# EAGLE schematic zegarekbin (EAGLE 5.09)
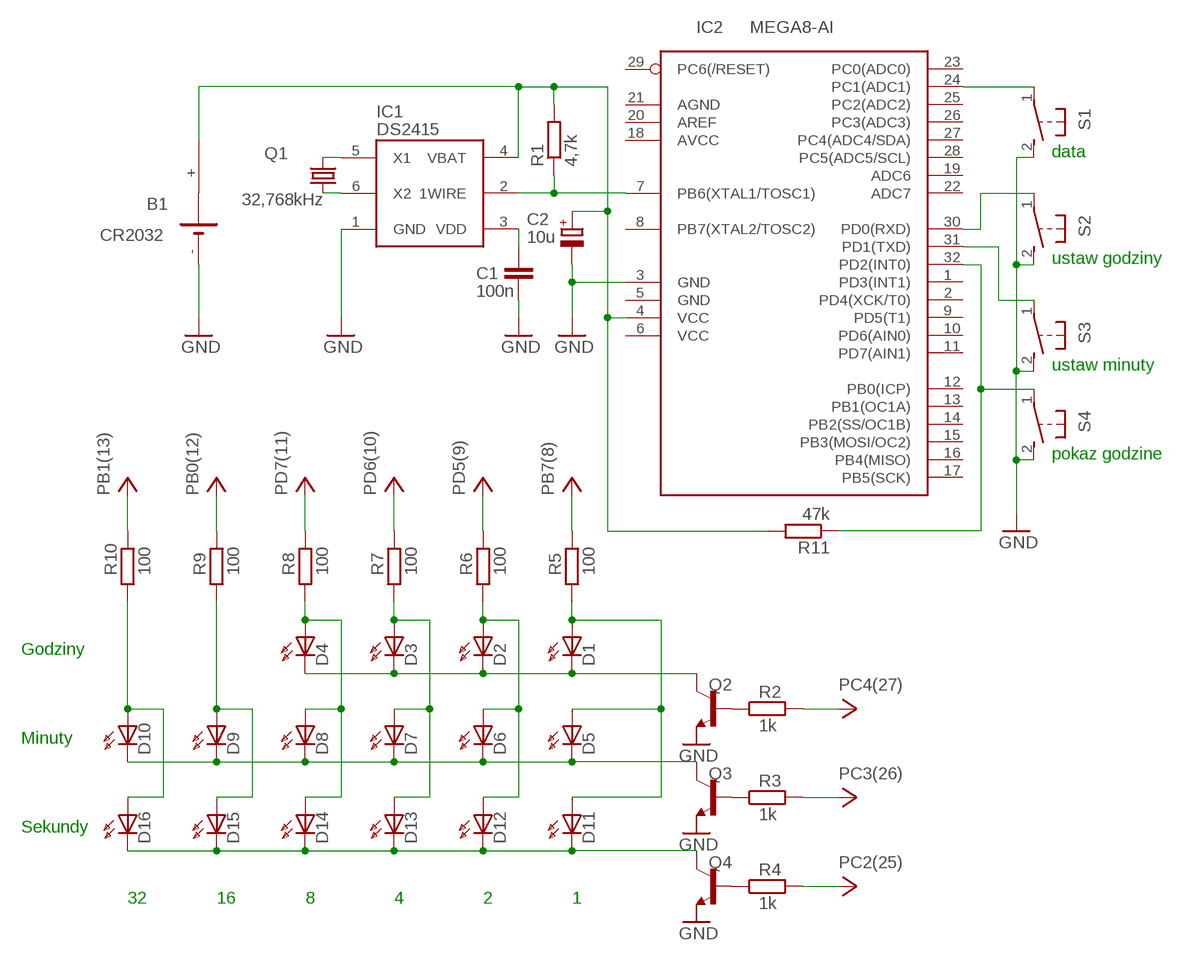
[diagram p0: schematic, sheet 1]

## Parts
B1  CR2032  B2430UNI  [B2430UNI]
C1  100n  C-EU025-024X044  [C025-024X044]
C2  10u  CPOL-EU085CS-1AR  [085CS_1AR]
D1  HLMP6  [HLMP6]
D2  HLMP6  [HLMP6]
D3  HLMP6  [HLMP6]
D4  HLMP6  [HLMP6]
D5  HLMP6  [HLMP6]
D6  HLMP6  [HLMP6]
D7  HLMP6  [HLMP6]
D8  HLMP6  [HLMP6]
D9  HLMP6  [HLMP6]
D10  HLMP6  [HLMP6]
D11  HLMP6  [HLMP6]
D12  HLMP6  [HLMP6]
D13  HLMP6  [HLMP6]
D14  HLMP6  [HLMP6]
D15  HLMP6  [HLMP6]
D16  HLMP6  [HLMP6]
IC1  DS2415  DS2417P  [TSOC6]
IC2  MEGA8-AI  [TQFP32-08]
Q1  32,768kHz  CRYSTAL68SMX  [86SMX]
Q2  BC547  [TO92]
Q3  BC547  [TO92]
Q4  BC547  [TO92]
R1  4,7k  R-EU_0204/2V  [0204V]
R2  1k  R-EU_0204/2V  [0204V]
R3  1k  R-EU_0204/2V  [0204V]
R4  1k  R-EU_0204/2V  [0204V]
R5  100  R-EU_0204/2V  [0204V]
R6  100  R-EU_0204/2V  [0204V]
R7  100  R-EU_0204/2V  [0204V]
R8  100  R-EU_0204/2V  [0204V]
R9  100  R-EU_0204/2V  [0204V]
R10  100  R-EU_0204/2V  [0204V]
R11  47k  R-EU_0204/2V  [0204V]
S1  31-XX  [B3F-31XX]
S2  31-XX  [B3F-31XX]
S3  31-XX  [B3F-31XX]
S4  31-XX  [B3F-31XX]

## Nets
GND: B1.- C1.2 C2.- IC1.1(GND) IC2.3(GND) S1.2(S) S2.2(S) S3.2(S) S4.2(S)
N$1: IC1.2(1WIRE) IC2.7(PB6(XTAL1/TOSC1)) R1.1
N$3: C1.1 IC1.3(VDD)
N$4: B1.+ C2.+ IC1.4(VBAT) IC2.4(VCC) R1.2 R11.2
N$5: IC1.5(X1) Q1.4
N$6: IC1.6(X2) Q1.1
N$7: IC2.31(PD1(TXD)) S3.1(P)
N$8: IC2.32(PD2(INT0)) R11.1 S4.1(P)
N$9: IC2.24(PC1(ADC1)) S1.1(P)
N$10: IC2.30(PD0(RXD)) S2.1(P)
N$11: Q2.2(B) R2.1
N$12: Q3.2(B) R3.1
N$13: Q4.2(B) R4.1
N$14: D1.K D2.K D3.K D4.K Q2.3(C)
N$15: D5.K D6.K D7.K D8.K D9.K D10.K Q3.3(C)
N$16: D11.K D12.K D13.K D14.K D15.K D16.K Q4.3(C)
N$18: D4.A D8.A D14.A R8.1
N$19: D3.A D7.A D13.A R7.1
N$20: D2.A D6.A D12.A R6.1
N$21: D1.A D5.A D11.A R5.1
N$22: D9.A D15.A R9.1
N$23: D10.A D16.A R10.1
PB1(13): R10.2
VCC: R2.2 R3.2 R4.2 R5.2 R6.2 R7.2 R8.2 R9.2 ; supply symbol labelled PC4(27), PC3(26), PC2(25), PB0(12), PD7(11), PD6(10), PD5(9), PB7(8)
Unconnected: B1.+@1(+) B1.+@2(+) B1.+@3(+) B1.+@4(+) B1.-@1(-) IC2.1(PD3(INT1)) IC2.2(PD4(XCK/T0)) IC2.5(GND) IC2.6(VCC) IC2.8(PB7(XTAL2/TOSC2)) IC2.9(PD5(T1)) IC2.10(PD6(AIN0)) IC2.11(PD7(AIN1)) IC2.12(PB0(ICP)) IC2.13(PB1(OC1A)) IC2.14(PB2(SS/OC1B)) IC2.15(PB3(MOSI/OC2)) IC2.16(PB4(MISO)) IC2.17(PB5(SCK)) IC2.18(AVCC) IC2.19(ADC6) IC2.20(AREF) IC2.21(AGND) IC2.22(ADC7) IC2.23(PC0(ADC0)) IC2.25(PC2(ADC2)) IC2.26(PC3(ADC3)) IC2.27(PC4(ADC4/SDA)) IC2.28(PC5(ADC5/SCL)) IC2.29(PC6(/RESET)) Q2.1(E) Q3.1(E) Q4.1(E)

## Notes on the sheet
- data
- ustaw godziny
- ustaw minuty
- pokaz godzine
- Godziny
- Minuty
- Sekundy
- 32 | 16 | 8 | 4 | 2 | 1

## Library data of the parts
B1 = battery:B2430UNI: LI BATTERY
C1 = rcl:C-EU: CAPACITOR, European symbol
C2 = rcl:CPOL-EU: POLARIZED CAPACITOR, European symbol
D1-D16 = display-hp:HLMP6: LED
IC1 = 1wire:DS2417: Time Chip With Interrupt This chip provides an RTC with time and date function. It operates with 2.5..5V at Vdd. The INT pin generates a low pulse every 1, 4, 32, 64, 2048, 4096, 65536, or 131072s (selectable by software). Notes: For proper operation the X1/X2 pins have to be connected to a 32768Hz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
IC2 = atmel:MEGA8: MICROCONTROLLER 8 Kbytes FLASH 1 kbytes SRAM 512 bytes EEPROM USART 6-channel 10 bit ADC 2-channel 8 bit ADC Source: avr.lbr
Q1 = crystal:CRYSTAL: CRYSTAL
Q2-Q4 = transistor-npn:BC547*: NPN Transistor
R1-R11 = rcl:R-EU_: RESISTOR, European symbol
S1-S4 = switch-omron:31-XX: OMRON SWITCH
